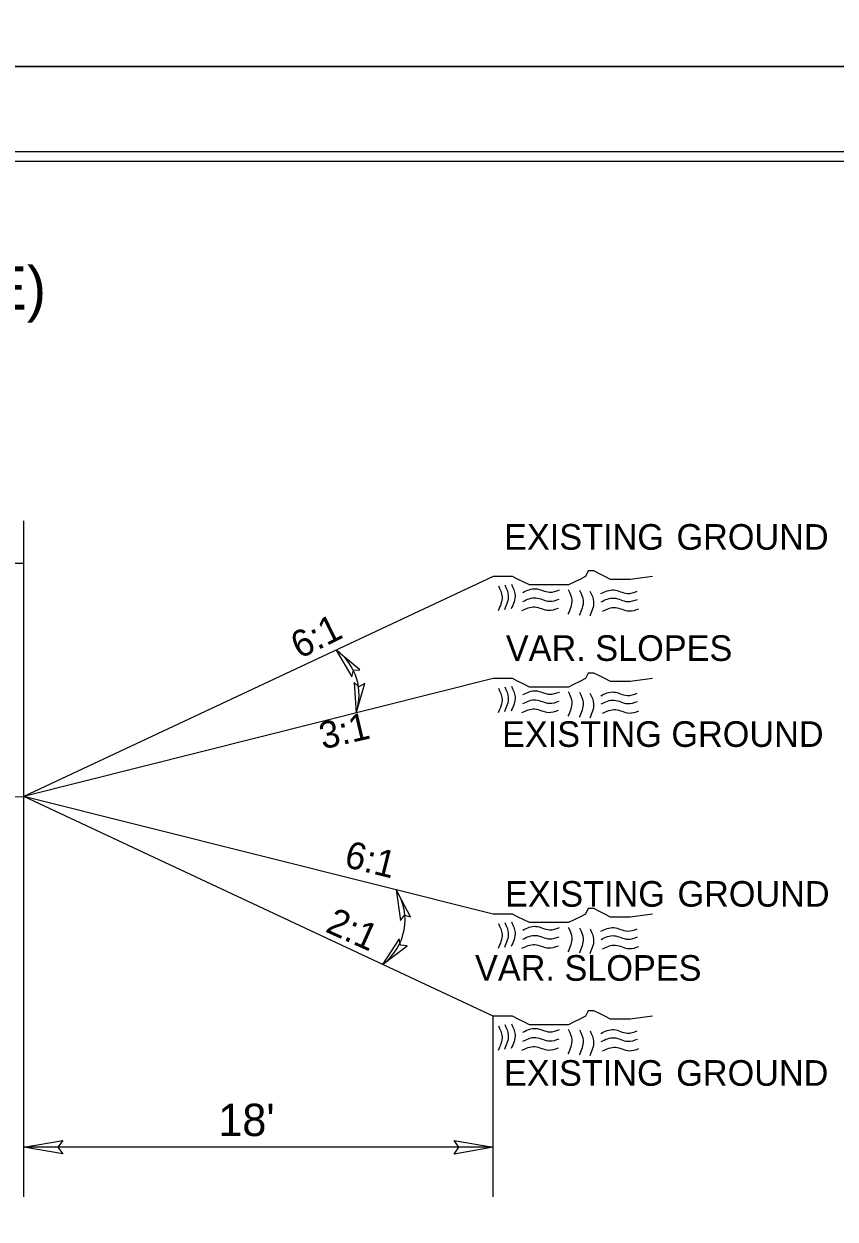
# Model space of a CAD drawing. Extents: x 573813 to 575363, y -54752 to -53123.
# Drawn here: x 574884.7 to 574927.5, y -53623.9 to -53560.8 of the extents above; entities that cross this region are included whole.
import ezdxf

# ---------------------------------------------------------------- set-up
doc = ezdxf.new("R2010")
doc.units = 0
for name, color, linetype in [('Old_Level_1', 7, 'Continuous'), ('Old_Level_11', 7, 'Continuous'), ('Old_Level_2', 7, 'Continuous'), ('Old_Level_3', 7, 'Continuous'), ('Sheet Cutting Line CELL', 7, 'Continuous'), ('Sheet Plot Border Inside CELL', 7, 'Continuous'), ('Sheet Plot Border Outside CELL', 7, 'Continuous'), ('Sheet Typical CELL', 7, 'Continuous'), ('Typical Terminator CELL', 7, 'Continuous')]:
    doc.layers.add(name, color=color, linetype=linetype)

msp = doc.modelspace()

# ---------------------------------------------------------------- linework, layer by layer
at = {"layer": 'Old_Level_1'}
for p in [(574909.465, -53589.971), (574909.465, -53595.353), (574877.577, -53601.709), (574909.465, -53607.778), (574909.465, -53613.16)]:
    msp.add_line(p, (574884.732, -53601.566), dxfattribs=at)
for points in [[(574917.871, -53589.971), (574916.692, -53590.118), (574916.397, -53590.118), (574915.954, -53590.118), (574915.659, -53590.118), (574915.364, -53589.971), (574915.069, -53589.823), (574914.774, -53589.675), (574914.479, -53589.675), (574914.331, -53589.971), (574914.036, -53590.118), (574913.742, -53590.266), (574913.447, -53590.413), (574913.152, -53590.413), (574912.857, -53590.413), (574912.562, -53590.413), (574912.267, -53590.413), (574911.972, -53590.413), (574911.677, -53590.413), (574911.382, -53590.413), (574911.087, -53590.266), (574910.793, -53590.118), (574910.498, -53589.971), (574910.055, -53589.971), (574909.76, -53589.971), (574909.465, -53589.971)], [(574917.872, -53595.354), (574916.692, -53595.5), (574916.397, -53595.5), (574915.954, -53595.5), (574915.659, -53595.5), (574915.364, -53595.353), (574915.069, -53595.205), (574914.774, -53595.057), (574914.479, -53595.057), (574914.331, -53595.353), (574914.036, -53595.5), (574913.742, -53595.648), (574913.447, -53595.795), (574913.152, -53595.795), (574912.857, -53595.795), (574912.562, -53595.795), (574912.267, -53595.795), (574911.972, -53595.795), (574911.677, -53595.795), (574911.382, -53595.795), (574911.087, -53595.648), (574910.793, -53595.5), (574910.498, -53595.353), (574910.055, -53595.353), (574909.76, -53595.353), (574909.465, -53595.353)], [(574917.872, -53607.778), (574916.692, -53607.925), (574916.397, -53607.925), (574915.954, -53607.925), (574915.659, -53607.925), (574915.364, -53607.778), (574915.07, -53607.63), (574914.774, -53607.482), (574914.48, -53607.482), (574914.332, -53607.778), (574914.037, -53607.925), (574913.742, -53608.073), (574913.447, -53608.22), (574913.152, -53608.219), (574912.857, -53608.22), (574912.562, -53608.219), (574912.267, -53608.22), (574911.972, -53608.219), (574911.677, -53608.22), (574911.382, -53608.219), (574911.088, -53608.073), (574910.793, -53607.924), (574910.498, -53607.778), (574910.055, -53607.778), (574909.76, -53607.778), (574909.465, -53607.778)], [(574917.872, -53613.16), (574916.692, -53613.307), (574916.397, -53613.307), (574915.954, -53613.307), (574915.659, -53613.307), (574915.364, -53613.16), (574915.07, -53613.012), (574914.775, -53612.864), (574914.48, -53612.864), (574914.332, -53613.16), (574914.037, -53613.307), (574913.742, -53613.455), (574913.447, -53613.602), (574913.152, -53613.602), (574912.857, -53613.602), (574912.562, -53613.602), (574912.267, -53613.602), (574911.972, -53613.602), (574911.678, -53613.602), (574911.383, -53613.602), (574911.088, -53613.455), (574910.793, -53613.307), (574910.498, -53613.16), (574910.055, -53613.16), (574909.76, -53613.16), (574909.465, -53613.16)]]:
    msp.add_lwpolyline(points, dxfattribs=at)
at = {"layer": 'Old_Level_11'}
for p, q in [((574884.732, -53601.145), (574884.731, -53587.032)), ((574884.731, -53589.288), (574871.088, -53589.288)), ((574884.732, -53622.684), (574884.732, -53601.145)), ((574909.465, -53622.683), (574909.465, -53613.16)), ((574909.465, -53620.068), (574884.732, -53620.068))]:
    msp.add_line(p, q, dxfattribs=at)
for points in [[(574886.778, -53620.421), (574884.732, -53620.068), (574886.789, -53619.704), (574886.528, -53620.068)], [(574907.418, -53619.715), (574909.465, -53620.068), (574907.407, -53620.432), (574907.668, -53620.068)]]:
    msp.add_lwpolyline(points, close=True, dxfattribs=at)
for centre, start, end in [((574899.484, -53596.209), 340.81548, 54.02862), ((574901.907, -53608.074), 306.28634, 32.7202)]:
    msp.add_arc(centre, 2.919, start, end, dxfattribs=at)
at = {"layer": 'Old_Level_2'}
for points in [[(574909.746, -53590.467), (574909.938, -53591.031), (574909.73, -53591.78)], [(574909.746, -53590.467), (574909.938, -53591.031), (574909.73, -53591.78)], [(574910.078, -53590.402), (574910.268, -53590.968), (574910.06, -53591.718)], [(574910.078, -53590.402), (574910.268, -53590.968), (574910.06, -53591.718)], [(574910.431, -53590.365), (574910.625, -53590.931), (574910.418, -53591.678)], [(574910.431, -53590.365), (574910.625, -53590.931), (574910.418, -53591.678)], [(574911.036, -53590.806), (574911.717, -53590.609), (574912.443, -53590.794), (574912.962, -53590.676)], [(574911.036, -53590.806), (574911.717, -53590.609), (574912.443, -53590.794), (574912.962, -53590.676)], [(574913.427, -53590.645), (574913.617, -53591.208), (574913.414, -53591.958)], [(574913.427, -53590.645), (574913.617, -53591.208), (574913.414, -53591.958)], [(574914.023, -53590.69), (574914.216, -53591.256), (574914.01, -53592.006)], [(574914.023, -53590.69), (574914.216, -53591.256), (574914.01, -53592.006)], [(574914.575, -53590.74), (574914.768, -53591.306), (574914.56, -53592.053)], [(574914.575, -53590.74), (574914.768, -53591.306), (574914.56, -53592.053)], [(574915.141, -53590.87), (574915.826, -53590.675), (574916.546, -53590.86), (574917.069, -53590.744)], [(574915.141, -53590.87), (574915.826, -53590.675), (574916.546, -53590.86), (574917.069, -53590.744)], [(574910.979, -53591.762), (574911.663, -53591.569), (574912.388, -53591.749), (574912.909, -53591.634)], [(574910.979, -53591.762), (574911.663, -53591.569), (574912.388, -53591.749), (574912.909, -53591.634)], [(574911.032, -53591.281), (574911.717, -53591.088), (574912.437, -53591.273), (574912.958, -53591.155)], [(574911.032, -53591.281), (574911.717, -53591.088), (574912.437, -53591.273), (574912.958, -53591.155)], [(574915.159, -53591.3), (574915.844, -53591.102), (574916.564, -53591.289), (574917.087, -53591.172)], [(574915.159, -53591.3), (574915.844, -53591.102), (574916.564, -53591.289), (574917.087, -53591.172)], [(574915.229, -53591.796), (574915.912, -53591.601), (574916.636, -53591.785), (574917.157, -53591.668)], [(574915.229, -53591.796), (574915.912, -53591.601), (574916.636, -53591.785), (574917.157, -53591.668)], [(574909.746, -53595.85), (574909.938, -53596.413), (574909.73, -53597.163)], [(574909.746, -53595.85), (574909.938, -53596.413), (574909.73, -53597.163)], [(574910.078, -53595.785), (574910.268, -53596.351), (574910.06, -53597.1)], [(574910.078, -53595.785), (574910.268, -53596.351), (574910.06, -53597.1)], [(574910.431, -53595.748), (574910.625, -53596.313), (574910.418, -53597.061)], [(574910.431, -53595.748), (574910.625, -53596.313), (574910.418, -53597.061)], [(574911.036, -53596.189), (574911.718, -53595.992), (574912.444, -53596.176), (574912.962, -53596.059)], [(574911.036, -53596.189), (574911.718, -53595.992), (574912.444, -53596.176), (574912.962, -53596.059)], [(574911.032, -53596.664), (574911.717, -53596.47), (574912.437, -53596.655), (574912.958, -53596.537)], [(574911.032, -53596.664), (574911.717, -53596.47), (574912.437, -53596.655), (574912.958, -53596.537)], [(574913.427, -53596.027), (574913.617, -53596.591), (574913.414, -53597.34)], [(574913.427, -53596.027), (574913.617, -53596.591), (574913.414, -53597.34)], [(574914.024, -53596.073), (574914.216, -53596.639), (574914.01, -53597.388)], [(574914.024, -53596.073), (574914.216, -53596.639), (574914.01, -53597.388)], [(574914.575, -53596.122), (574914.768, -53596.688), (574914.56, -53597.435)], [(574914.575, -53596.122), (574914.768, -53596.688), (574914.56, -53597.435)], [(574915.141, -53596.253), (574915.826, -53596.058), (574916.546, -53596.242), (574917.069, -53596.127)], [(574915.141, -53596.253), (574915.826, -53596.058), (574916.546, -53596.242), (574917.069, -53596.127)], [(574915.159, -53596.682), (574915.844, -53596.485), (574916.564, -53596.671), (574917.087, -53596.554)], [(574915.159, -53596.682), (574915.844, -53596.485), (574916.564, -53596.671), (574917.087, -53596.554)], [(574910.979, -53597.144), (574911.663, -53596.951), (574912.389, -53597.132), (574912.909, -53597.016)], [(574910.979, -53597.144), (574911.663, -53596.951), (574912.389, -53597.132), (574912.909, -53597.016)], [(574915.229, -53597.178), (574915.912, -53596.983), (574916.636, -53597.167), (574917.157, -53597.05)], [(574915.229, -53597.178), (574915.912, -53596.983), (574916.636, -53597.167), (574917.157, -53597.05)], [(574909.746, -53608.274), (574909.938, -53608.838), (574909.73, -53609.587)], [(574909.746, -53608.274), (574909.938, -53608.838), (574909.73, -53609.587)], [(574910.078, -53608.209), (574910.268, -53608.775), (574910.06, -53609.525)], [(574910.078, -53608.209), (574910.268, -53608.775), (574910.06, -53609.525)], [(574910.431, -53608.172), (574910.626, -53608.738), (574910.418, -53609.485)], [(574910.431, -53608.172), (574910.626, -53608.738), (574910.418, -53609.485)], [(574911.036, -53608.613), (574911.718, -53608.416), (574912.444, -53608.6), (574912.962, -53608.483)], [(574911.036, -53608.613), (574911.718, -53608.416), (574912.444, -53608.6), (574912.962, -53608.483)], [(574913.427, -53608.451), (574913.618, -53609.015), (574913.414, -53609.764)], [(574913.427, -53608.451), (574913.618, -53609.015), (574913.414, -53609.764)], [(574914.024, -53608.497), (574914.216, -53609.063), (574914.01, -53609.812)], [(574914.024, -53608.497), (574914.216, -53609.063), (574914.01, -53609.812)], [(574914.576, -53608.547), (574914.768, -53609.113), (574914.56, -53609.86)], [(574914.576, -53608.547), (574914.768, -53609.113), (574914.56, -53609.86)], [(574915.141, -53608.677), (574915.827, -53608.482), (574916.547, -53608.666), (574917.069, -53608.551)], [(574915.141, -53608.677), (574915.827, -53608.482), (574916.547, -53608.666), (574917.069, -53608.551)], [(574911.032, -53609.088), (574911.718, -53608.895), (574912.438, -53609.079), (574912.958, -53608.962)], [(574911.032, -53609.088), (574911.718, -53608.895), (574912.438, -53609.079), (574912.958, -53608.962)], [(574915.159, -53609.106), (574915.845, -53608.909), (574916.565, -53609.096), (574917.087, -53608.978)], [(574915.159, -53609.106), (574915.845, -53608.909), (574916.565, -53609.096), (574917.087, -53608.978)], [(574910.979, -53609.569), (574911.663, -53609.376), (574912.389, -53609.556), (574912.909, -53609.441)], [(574910.979, -53609.569), (574911.663, -53609.376), (574912.389, -53609.556), (574912.909, -53609.441)], [(574915.229, -53609.603), (574915.912, -53609.407), (574916.636, -53609.592), (574917.157, -53609.474)], [(574915.229, -53609.603), (574915.912, -53609.407), (574916.636, -53609.592), (574917.157, -53609.474)], [(574909.746, -53613.656), (574909.938, -53614.22), (574909.73, -53614.969)], [(574909.746, -53613.656), (574909.938, -53614.22), (574909.73, -53614.969)], [(574910.078, -53613.591), (574910.268, -53614.157), (574910.061, -53614.907)], [(574910.078, -53613.591), (574910.268, -53614.157), (574910.061, -53614.907)], [(574910.432, -53613.554), (574910.626, -53614.12), (574910.418, -53614.867)], [(574910.432, -53613.554), (574910.626, -53614.12), (574910.418, -53614.867)], [(574911.032, -53614.47), (574911.718, -53614.277), (574912.438, -53614.462), (574912.958, -53614.344)], [(574911.032, -53614.47), (574911.718, -53614.277), (574912.438, -53614.462), (574912.958, -53614.344)], [(574911.036, -53613.995), (574911.718, -53613.798), (574912.444, -53613.983), (574912.962, -53613.865)], [(574911.036, -53613.995), (574911.718, -53613.798), (574912.444, -53613.983), (574912.962, -53613.865)], [(574913.427, -53613.834), (574913.618, -53614.398), (574913.414, -53615.147)], [(574913.427, -53613.834), (574913.618, -53614.398), (574913.414, -53615.147)], [(574914.024, -53613.879), (574914.216, -53614.445), (574914.01, -53615.195)], [(574914.024, -53613.879), (574914.216, -53614.445), (574914.01, -53615.195)], [(574914.576, -53613.929), (574914.768, -53614.495), (574914.56, -53615.242)], [(574914.576, -53613.929), (574914.768, -53614.495), (574914.56, -53615.242)], [(574915.141, -53614.059), (574915.827, -53613.864), (574916.547, -53614.049), (574917.069, -53613.933)], [(574915.141, -53614.059), (574915.827, -53613.864), (574916.547, -53614.049), (574917.069, -53613.933)], [(574915.159, -53614.489), (574915.845, -53614.292), (574916.565, -53614.478), (574917.087, -53614.361)], [(574915.159, -53614.489), (574915.845, -53614.292), (574916.565, -53614.478), (574917.087, -53614.361)], [(574910.979, -53614.951), (574911.663, -53614.758), (574912.389, -53614.939), (574912.909, -53614.823)], [(574910.979, -53614.951), (574911.663, -53614.758), (574912.389, -53614.939), (574912.909, -53614.823)], [(574915.229, -53614.985), (574915.913, -53614.79), (574916.636, -53614.974), (574917.157, -53614.857)], [(574915.229, -53614.985), (574915.913, -53614.79), (574916.636, -53614.974), (574917.157, -53614.857)]]:
    msp.add_spline(points, degree=3, dxfattribs=at)
at = {"layer": 'Sheet Cutting Line CELL'}
for p, q in [((575006.712, -53563.07), (574669.731, -53563.07)), ((574669.731, -53563.07), (575006.712, -53563.07))]:
    msp.add_line(p, q, dxfattribs=at)
at = {"layer": 'Sheet Plot Border Inside CELL'}
msp.add_lwpolyline([(575005.811, -53567.563), (574672.332, -53567.563), (574672.332, -53778.696), (575005.811, -53778.696)], close=True, dxfattribs=at)
at = {"layer": 'Sheet Plot Border Outside CELL'}
for p, q in [((574669.731, -53563.07), (575006.712, -53563.07)), ((575006.712, -53563.07), (574669.731, -53563.07))]:
    msp.add_line(p, q, dxfattribs=at)
for points in [[(575006.712, -53342.952), (574669.731, -53342.952), (574669.731, -53563.07), (575006.712, -53563.07)], [(575006.712, -53563.07), (574669.731, -53563.07), (574669.731, -53783.189), (575006.712, -53783.189)]]:
    msp.add_lwpolyline(points, close=True, dxfattribs=at)
at = {"layer": 'Sheet Typical CELL'}
msp.add_lwpolyline([(575003.31, -53568.073), (574703.149, -53568.073), (574703.149, -53778.186), (575003.31, -53778.186)], close=True, dxfattribs=at)
at = {"layer": 'Typical Terminator CELL'}
for points in [[(574902.434, -53594.884), (574901.198, -53593.846), (574902.015, -53595.25), (574902.099, -53594.912)], [(574902.145, -53595.557), (574902.241, -53597.168), (574902.699, -53595.61), (574902.395, -53595.781)], [(574905.12, -53607.922), (574904.363, -53606.496), (574904.594, -53608.104), (574904.799, -53607.823)], [(574904.516, -53609.075), (574903.635, -53610.427), (574904.93, -53609.448), (574904.585, -53609.404)]]:
    msp.add_lwpolyline(points, close=True, dxfattribs=at)

# ---------------------------------------------------------------- texts
at = {"layer": 'Old_Level_1'}
for s, height, rotation, p in [('EXISTING ', 1.3502, 359.99996, (574910.047, -53588.554)), ('GROUND', 1.3502, 359.99996, (574919.134, -53588.554)), ('6:1', 1.4212, 26.33203, (574899.263, -53594.336)), ('VAR. SLOPES', 1.35016, 359.99996, (574910.139, -53594.417)), ('3:1', 1.4212, 13.17004, (574900.488, -53599.092)), ('EXISTING GROUND', 1.35016, 359.99996, (574909.938, -53598.952)), ('6:1', 1.4212, 346.10025, (574901.561, -53605.259)), ('EXISTING ', 1.3502, 359.99996, (574910.098, -53607.378)), ('GROUND', 1.3502, 359.99996, (574919.185, -53607.378)), ('2:1', 1.4212, 335.83189, (574900.566, -53608.675)), ('VAR. SLOPES', 1.35016, 359.99996, (574908.514, -53611.285)), ('EXISTING ', 1.3502, 359.99996, (574910.033, -53616.824)), ('GROUND', 1.3502, 359.99996, (574919.12, -53616.824))]:
    msp.add_text(s, height=height, rotation=rotation, dxfattribs=at).set_placement(p)
at = {"layer": 'Old_Level_11'}
msp.add_text("18'", height=1.7055, rotation=359.99996, dxfattribs=at).set_placement((574894.978, -53619.476))
at = {"layer": 'Old_Level_3'}
msp.add_text('-YLPA- (REVERSE)', height=2.27395, rotation=0, dxfattribs=at).set_placement((574858.697, -53575.891))

doc.saveas('drawing.dxf')
